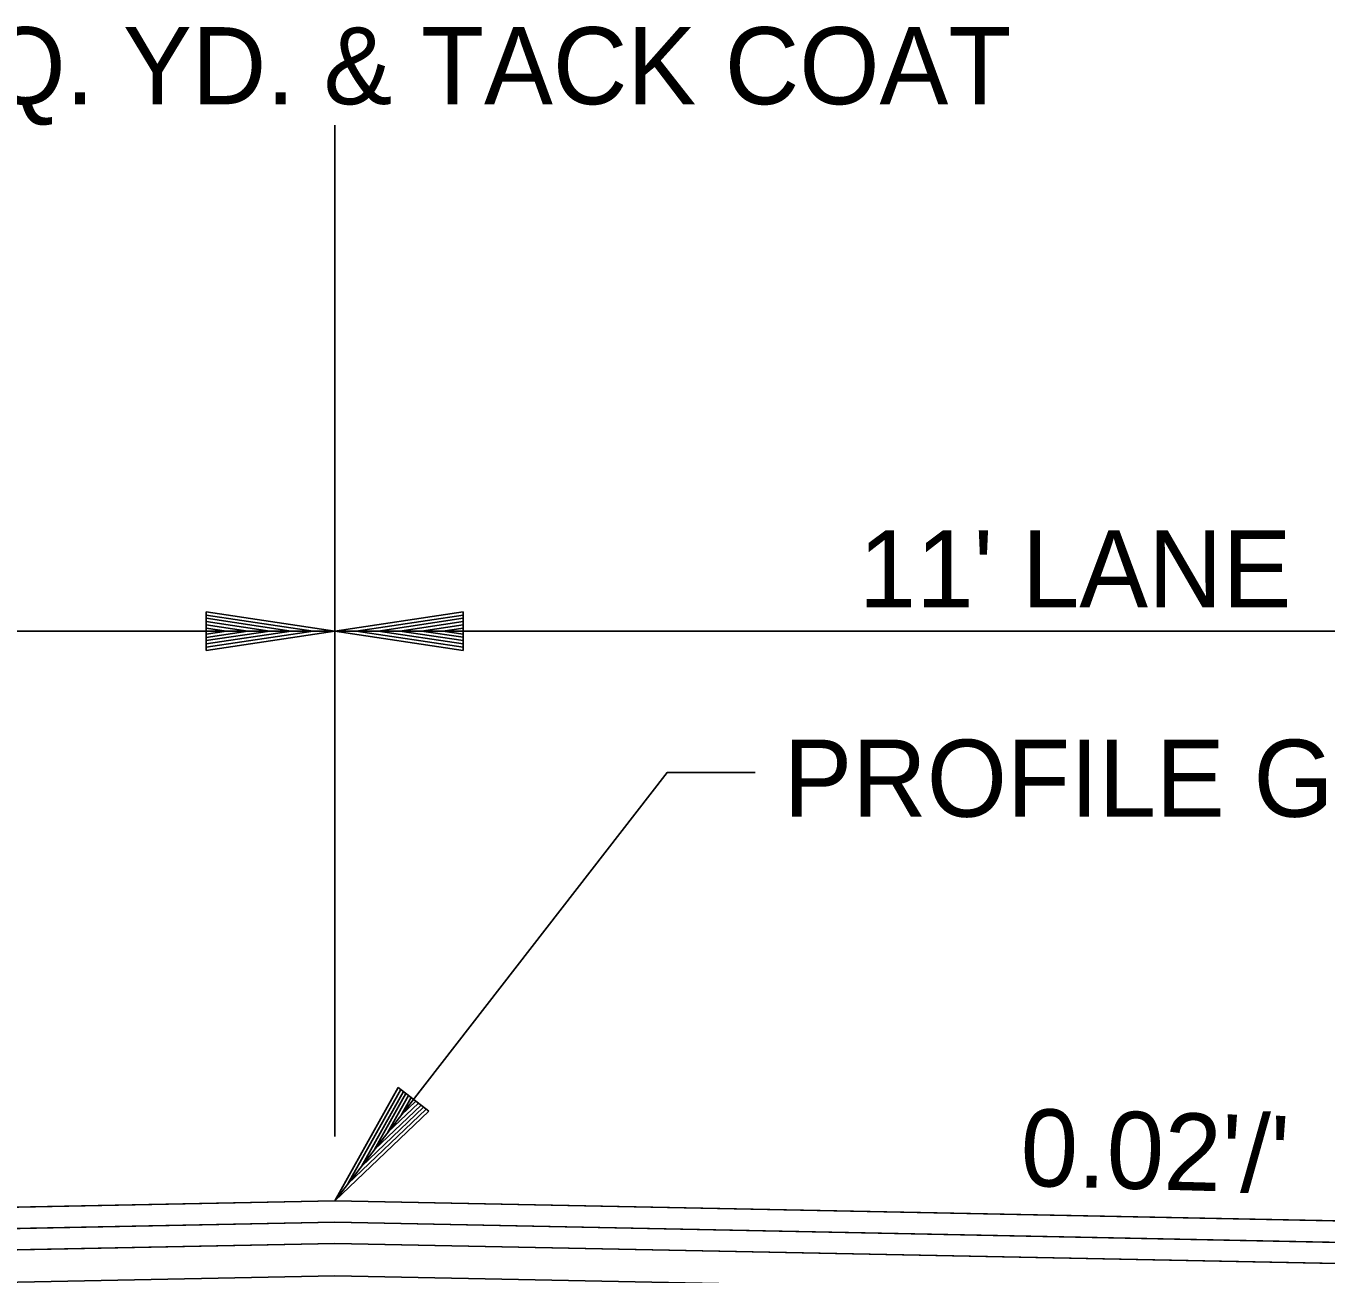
# Model space of a CAD drawing. Extents: x 2478 to 3210, y 439 to 841.
# Drawn here: x 2622.23 to 2642.46, y 489.09 to 508.51 of the extents above; entities that cross this region are included whole.
import ezdxf

# ---------------------------------------------------------------- set-up
doc = ezdxf.new("R2010")
doc.units = 0
for name, color, linetype in [('19', 7, 'Continuous'), ('R_Annotation', 7, 'Continuous'), ('R_Centerline', 7, 'Continuous'), ('R_Dimension', 7, 'Continuous')]:
    doc.layers.add(name, color=color, linetype=linetype)

msp = doc.modelspace()

# ---------------------------------------------------------------- linework, layer by layer
at = {"layer": '19'}
for points in [[(2601.034, 489.627), (2600.864, 489.287), (2604.864, 489.447), (2627.034, 489.894), (2649.204, 489.447), (2653.204, 489.287), (2653.034, 489.627), (2649.034, 489.787), (2627.034, 490.227), (2605.034, 489.787)], [(2604.864, 489.447), (2604.697, 489.114), (2627.034, 489.561), (2649.371, 489.114), (2649.204, 489.447), (2627.034, 489.894)], [(2604.697, 489.114), (2604.445, 488.609), (2627.034, 489.061), (2649.623, 488.609), (2649.371, 489.114), (2627.034, 489.561)]]:
    msp.add_lwpolyline(points, close=True, dxfattribs=at)
at = {"layer": 'R_Annotation'}
for p, q in [((2605.034, 489.787), (2627.034, 490.227)), ((2649.034, 489.787), (2627.034, 490.227)), ((2604.864, 489.447), (2627.034, 489.894)), ((2649.204, 489.447), (2627.034, 489.894)), ((2604.697, 489.114), (2627.034, 489.561)), ((2649.371, 489.114), (2627.034, 489.561))]:
    msp.add_line(p, q, dxfattribs=at)
at = {"layer": 'R_Centerline'}
msp.add_line((2627.034, 491.228), (2627.034, 506.97), dxfattribs=at)
at = {"layer": 'R_Dimension'}
for p, q in [((2625.034, 499.394), (2627.034, 499.094)), ((2625.034, 499.394), (2625.034, 498.794)), ((2625.034, 499.344), (2626.7, 499.094)), ((2629.034, 499.394), (2627.034, 499.094)), ((2629.034, 499.344), (2627.368, 499.094)), ((2629.034, 498.794), (2629.034, 499.394)), ((2625.034, 499.293), (2626.356, 499.094)), ((2625.034, 499.243), (2626.023, 499.094)), ((2625.034, 499.191), (2625.684, 499.094)), ((2629.034, 499.293), (2627.712, 499.094)), ((2629.034, 499.243), (2628.045, 499.094)), ((2629.034, 499.192), (2628.384, 499.094)), ((2666.487, 499.094), (2587.581, 499.094)), ((2625.034, 499.141), (2625.35, 499.094)), ((2625.034, 498.794), (2627.034, 499.094)), ((2625.034, 498.996), (2625.684, 499.094)), ((2625.034, 498.895), (2626.356, 499.094)), ((2625.034, 498.844), (2626.7, 499.094)), ((2625.034, 498.945), (2626.023, 499.094)), ((2625.034, 499.047), (2625.35, 499.094)), ((2629.034, 498.794), (2627.034, 499.094)), ((2629.034, 498.844), (2627.368, 499.094)), ((2629.034, 498.895), (2627.712, 499.094)), ((2629.034, 498.945), (2628.045, 499.094)), ((2629.034, 498.997), (2628.384, 499.094)), ((2629.034, 499.141), (2628.718, 499.094)), ((2629.034, 499.047), (2628.718, 499.094)), ((2628.023, 491.992), (2627.034, 490.227)), ((2628.062, 491.961), (2627.239, 490.491)), ((2628.103, 491.93), (2627.45, 490.763)), ((2628.142, 491.899), (2627.654, 491.026)), ((2628.182, 491.868), (2627.861, 491.294)), ((2628.497, 491.624), (2628.023, 491.992)), ((2628.417, 491.686), (2627.45, 490.763)), ((2628.378, 491.716), (2627.654, 491.026)), ((2628.336, 491.748), (2627.861, 491.294)), ((2628.223, 491.837), (2628.066, 491.558)), ((2628.297, 491.779), (2628.066, 491.558)), ((2628.497, 491.624), (2627.034, 490.227)), ((2628.457, 491.655), (2627.239, 490.491))]:
    msp.add_line(p, q, dxfattribs=at)
msp.add_lwpolyline([(2627.034, 490.227), (2632.204, 496.892), (2633.576, 496.892)], dxfattribs=at)

# ---------------------------------------------------------------- texts
at = {"layer": 'R_Annotation'}
for s, p in [('330 LBS. PER SQ. YD. & TACK COAT', (2609.737, 507.294)), ("11' LANE", (2635.188, 499.462)), ('PROFILE GRADE', (2634.016, 496.204))]:
    msp.add_text(s, height=1.2, dxfattribs=at).set_placement(p)
msp.add_text("0.02'/'", height=1.2, rotation=358.3978, dxfattribs=at).set_placement((2637.691, 490.462))

doc.saveas('drawing.dxf')
